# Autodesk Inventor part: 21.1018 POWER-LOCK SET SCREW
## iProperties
Created: 2006-02
Material: Steel, Mild
Description: Hexagon Socket Set Screw
Document SubType Name: Modeling
Standard: DIN 913
Designer: Andy Moles
Standards Organization: DIN
Language: en-US
Size Designation: M8 x 16
Categories: <MemberInstance><Categories><Category DisplayName="Fasteners" InternalName="e4da775c-781d-43d5-af7c-5136215cf5a6" Mnemonic="FSTN"><Category DisplayName="Bolts"
Density: 7.86 g/cm^3
Mass: 5.61117 g
Surface Area: 5.51599 cm^2
Volume: 0.713889 cm^3
Part Number: 21.1018 POWER-LOCK SET SCREW
Author: Andy Moles
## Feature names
1. Body [Revolution]
2. Slot [Extrusion]
3. Chamfer1
4. Chamfer2
